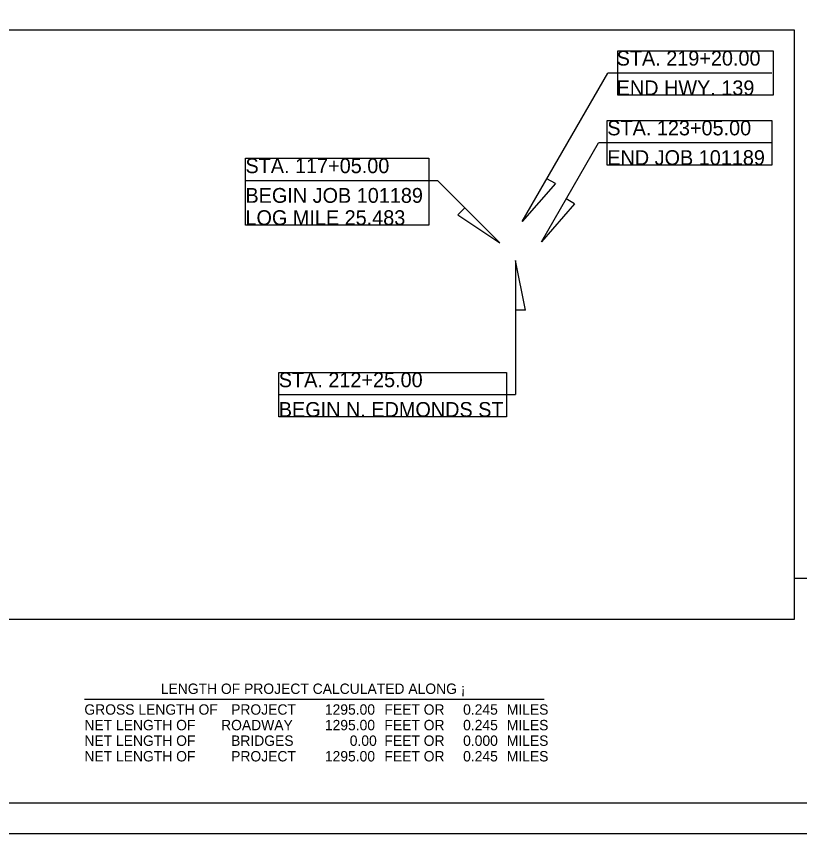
# Model space of a CAD drawing. Extents: x -0.54 to 1.64, y 0 to 0.92.
# Drawn here: x 0.528 to 1.056, y 0 to 0.551 of the extents above; entities that cross this region are included whole.
import ezdxf

# ---------------------------------------------------------------- set-up
doc = ezdxf.new("R2010")
doc.units = 0
for name, color, linetype in [('DSN_DRFT_DNC', 7, 'Continuous'), ('SHET_Annotations', 7, 'Continuous'), ('SHET_Border-Lines', 7, 'Continuous'), ('SHET_Border-Text', 7, 'Continuous')]:
    doc.layers.add(name, color=color, linetype=linetype)

msp = doc.modelspace()

# ---------------------------------------------------------------- linework, layer by layer
at = {"layer": 'DSN_DRFT_DNC'}
msp.add_lwpolyline([(0.4056, 0.54167), (1.05273, 0.54167), (1.05273, 0.1443), (0.4056, 0.1443)], close=True, dxfattribs=at)
at = {"layer": 'SHET_Annotations'}
for p, q in [((0.8692, 0.41256), (0.92699, 0.51265)), ((1.03757, 0.51265), (0.92699, 0.51265)), ((0.88217, 0.39895), (0.92066, 0.46563)), ((1.03757, 0.46563), (0.92066, 0.46563)), ((0.89165, 0.43807), (0.88586, 0.44141)), ((0.68262, 0.44015), (0.81222, 0.44015)), ((0.8541, 0.39828), (0.81222, 0.44015)), ((0.89165, 0.43807), (0.8692, 0.41256)), ((0.90462, 0.42446), (0.88217, 0.39895)), ((0.90462, 0.42446), (0.89883, 0.4278)), ((0.82581, 0.41711), (0.83054, 0.42184)), ((0.82581, 0.41711), (0.8541, 0.39828)), ((0.87142, 0.35291), (0.86473, 0.38623)), ((0.86473, 0.38623), (0.86473, 0.29588)), ((0.87142, 0.35291), (0.86473, 0.35291)), ((0.7051, 0.29588), (0.86473, 0.29588)), ((1.05273, 0.17226), (1.07773, 0.17226))]:
    msp.add_line(p, q, dxfattribs=at)
at = {"layer": 'SHET_Border-Lines'}
for points in [[(0, 0), (1.41667, 0), (1.41667, 0.91667), (0, 0.91667)], [(0.04167, 0.02083), (1.39583, 0.02083), (1.39583, 0.89583), (0.04167, 0.89583)]]:
    msp.add_lwpolyline(points, close=True, dxfattribs=at)
at = {"layer": 'SHET_Border-Text'}
msp.add_line((0.57417, 0.09067), (0.88417, 0.09067), dxfattribs=at)
for points in [[(0.93383, 0.52765), (1.03844, 0.52765), (1.03844, 0.49765), (0.93383, 0.49765)], [(0.92664, 0.48063), (1.03757, 0.48063), (1.03757, 0.45063), (0.92664, 0.45063)], [(0.68262, 0.45515), (0.80624, 0.45515), (0.80624, 0.41015), (0.68262, 0.41015)], [(0.7051, 0.31088), (0.85875, 0.31088), (0.85875, 0.28088), (0.7051, 0.28088)]]:
    msp.add_lwpolyline(points, close=True, dxfattribs=at)

# ---------------------------------------------------------------- texts
at = {"layer": 'SHET_Annotations'}
for s, p in [('1295.00', (0.73617, 0.08017)), ('0.245 ', (0.82941, 0.08017)), ('MILES', (0.85885, 0.08017)), ('1295.00', (0.73617, 0.06967)), ('0.245 ', (0.82941, 0.06967)), ('MILES', (0.85885, 0.06967)), ('0.00', (0.75295, 0.05917)), ('0.000 ', (0.82941, 0.05917)), ('MILES', (0.85885, 0.05917)), ('1295.00', (0.73617, 0.04867)), ('0.245 ', (0.82941, 0.04867)), ('MILES', (0.85885, 0.04867))]:
    msp.add_text(s, height=0.007, dxfattribs=at).set_placement(p)
at = {"layer": 'SHET_Border-Text'}
for s, height, p in [('STA. 219+20.00', 0.01, (0.93296, 0.51765)), ('END HWY. 139', 0.01, (0.93296, 0.49765)), ('STA. 123+05.00', 0.01, (0.92664, 0.47063)), ('END JOB 101189', 0.01, (0.92664, 0.45063)), ('STA. 117+05.00', 0.01, (0.68262, 0.44515)), ('BEGIN JOB 101189', 0.01, (0.68262, 0.42515)), ('LOG MILE 25.483', 0.01, (0.68262, 0.41015)), ('STA. 212+25.00', 0.01, (0.7051, 0.30088)), ('BEGIN N. EDMONDS ST', 0.01, (0.7051, 0.28088)), ('LENGTH OF PROJECT CALCULATED ALONG ¡', 0.007, (0.62551, 0.09417)), ('GROSS LENGTH OF', 0.007, (0.57399, 0.08017)), ('PROJECT', 0.007, (0.67296, 0.08017)), ('FEET OR', 0.007, (0.77631, 0.08017)), ('NET LENGTH OF', 0.007, (0.57399, 0.06967)), ('ROADWAY', 0.007, (0.66618, 0.06967)), ('FEET OR', 0.007, (0.77631, 0.06967)), ('NET LENGTH OF', 0.007, (0.57399, 0.05917)), ('BRIDGES', 0.007, (0.67293, 0.05917)), ('FEET OR', 0.007, (0.77631, 0.05917)), ('NET LENGTH OF', 0.007, (0.57399, 0.04867)), ('PROJECT', 0.007, (0.67296, 0.04867)), ('FEET OR', 0.007, (0.77631, 0.04867))]:
    msp.add_text(s, height=height, dxfattribs=at).set_placement(p)

doc.saveas('drawing.dxf')
